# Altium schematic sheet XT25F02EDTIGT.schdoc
size 127 x 101 mm
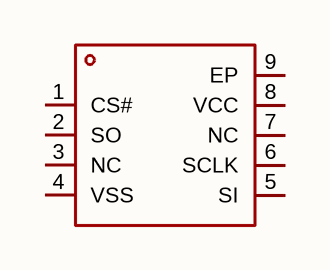
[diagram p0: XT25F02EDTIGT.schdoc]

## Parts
U?  xt25f02edtigt  [DFN-8_L3.0-W2.0-P0.50-BL-EP_XT25]  (value not drawn)

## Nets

Not connected (* = marked no-connect by the designer): U? 1(CS#) 2(SO) 3(NC) 4(VSS) 5(SI) 6(SCLK) 7(NC) 8(VCC) 9(EP)

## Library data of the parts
U? = xt25f02edtigt: 接口类型:SPI;存储容量:2Mbit;时钟频率(fc):120MHz;; Manufacturer: XTX(芯天下); AddInBom: yes; ModelId: 5c98a16e99044ad9a3bbd0d76d1453c7; ModelTransform: 79.527,118.8974,0,0,0,0,0,0,0; Interface: SPI; Memory Size: 2Mbit; Clock Frequency: 120MHz; Voltage - Supply: 2.7V~3.6V; Standby Supply Current: 13uA; Program / Erase Cycles: 100000次; Page Programming Time (Tpp): 1.3ms; Block Erase Time(tBE): 500ms@(64KB); Data Retention - TDR (Year): 20年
